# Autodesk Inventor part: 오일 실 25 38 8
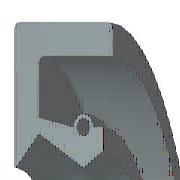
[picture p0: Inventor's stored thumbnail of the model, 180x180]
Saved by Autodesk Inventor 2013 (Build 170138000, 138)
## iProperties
Created: 2012-02
Part Number: 오일 실 25 38 8
Material: 고무
Description: 오일-실
Document SubType Name: Modeling
Standard: KS B 2804
Designer: mduedu
Standards Organization: KS
Language: ko-KR
Size Designation: D - 25 38 8
Categories: <MemberInstance><Categories><Category DisplayName="샤프트 부품" InternalName="7f7aeb1f-a693-4053-b835-cee3144e0d98" Mnemonic="SHFT"><Category DisplayName="실링" Intern
Density: 0.93 g/cm^3
IsCustomPart: 1
Author: mduedu
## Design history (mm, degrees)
revolve "본체" stored, may be unused: angle "d17" = 90 deg
revolve "스프링1" stored, may be unused: angle "d18" = 90 deg
body "Solid1"
sketch "스케치1"
  geometry: L1 (0, 19)-(8, 19); L2 (8, 17.25)-(1.75, 17.25); L3 (1.75, 14.25)-(4.9, 12.5); L4 (4.9, 12.5)-(0, 12.5); L5 (0, 0)-(9.586, 0) reference; L6 (4.9, 12.5)-(6.3, 13.375); L7 (0, 18)-(0, -3) reference; L8 (-1.941, 0)-(11.507, 0) reference; L9 (4.2, 14.6)-(1.75, 15.21); L10 (1.75, 15.21)-(1.75, 17.25); L11 (0, 19)-(0, 12.588); L12 (4.9, 12.5)-(0, 12.5); L13 (1.75, 14.25)-(0.152, 12.528); L14 (8, 19)-(8, 17.25); L15 (5.6, 14.6)-(6.3, 14.6); L16 (6.3, 14.6)-(6.3, 13.375); C1 r 0.455 at (4.9, 14.6); A1 r 0.7 centre (4.9, 14.6) between (5.6, 14.6) and (4.2, 14.6); A2 r 0.088 centre (0.087, 12.588) between (0, 12.588) and (0.152, 12.528); 1 further point
  constraints: 28 end point, 5 horizontal alignment, 5 point on line, 4 point on circle, 4 vertical alignment, 3 centre point, 3 tangent, 2 collinear, 2 horizontal, 2 perpendicular, 1 coincident, 1 parallel
  dimensions: "d0" = 38 diameter of L1 L5 (= SD2); "d1" = 1.75 distance of L1.end L2.start (= SD); "d2" = 0.91 diameter of C1 (= SPDI); "d3" = 1.4 diameter of A1 (= SPDA); "d4" = 25 diameter of L3.end L5 (= NND); "d5" = 28.5 diameter of L3.start L5 (= TKDM); "d7" = 30.42 diameter of L9.end L5 (= TKDM + 0.24 x SWDT); "d8" = 1.75 distance between parallel lines of L11 L10 (= SD); "d9" = 4.9 distance from line of L11 C1.centre (= SPDST); "d10" = 29.2 diameter of C1.centre L5 (= HLDM); "d11" = 0.0875 radius of A2 (= 0.25 x LAB); "d12" = 6.3 distance between parallel lines of L11 L16 (= SDI); "d13" = 26.75 diameter of L6.end L5 (= ABDM); "d14" = 8 distance from line of L11 L1.end (= SWDT)
fillet "모깎기1" dims "d6" = 0.3 (= RR)
other parameters: "SD2" = 38 [user parameter; used in 1 equation term], "SWDT" = 8 [user parameter; used in 2 equation terms], "RR" = 0.3 [user parameter; used in 1 equation term], "SD" = 1.75 [user parameter; used in 2 equation terms], "NND" = 25 [user parameter; used in 1 equation term], "SPDA" = 1.4 [user parameter; used in 1 equation term], "SPDI" = 0.91 [user parameter; used in 1 equation term], "TKDM" = 28.5 [user parameter; used in 2 equation terms], "HLDM" = 29.2 [user parameter; used in 1 equation term], "ABDM" = 26.75 [user parameter; used in 1 equation term], "SDI" = 6.3 [user parameter; used in 1 equation term], "SPDST" = 4.9 [user parameter; used in 1 equation term], "LAB" = 0.35 [user parameter; used in 1 equation term], "d15" = 0, "d16" = 0, "d19" = 0
